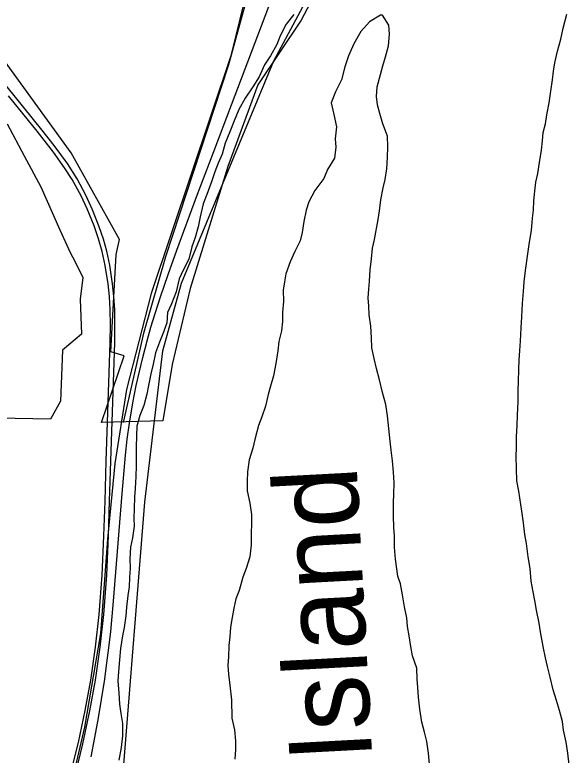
# Model space of a CAD drawing. Extents: x 0 to 34, y 0 to 22.
# Drawn here: x 7.567 to 8.202, y 16.72 to 17.57 of the extents above; entities that cross this region are included whole.
import ezdxf

# ---------------------------------------------------------------- set-up
doc = ezdxf.new("R2010")
doc.units = 0
for name, color, linetype in [('Default', 7, 'Continuous'), ('GM_X_Corporation', 7, 'Continuous'), ('GM_X_County_Road', 7, 'Continuous'), ('GM_X_Major_River', 7, 'Continuous'), ('GM_X_Major_River_Text', 7, 'Continuous'), ('GM_X_Rail_Line', 7, 'Continuous'), ('GM_X_State_Route', 7, 'Continuous'), ('SH_Cut_Line', 7, 'Continuous')]:
    doc.layers.add(name, color=color, linetype=linetype)

msp = doc.modelspace()

# ---------------------------------------------------------------- linework, layer by layer
at = {"layer": 'Default'}
for p, q in [((7.86366, 17.51672), (7.97349, 17.7219)), ((7.7577, 17.26163), (7.86366, 17.51672)), ((7.73627, 17.18403), (7.7577, 17.26163)), ((7.7159, 17.01051), (7.73627, 17.18403)), ((7.68935, 16.68153), (7.7159, 17.01051))]:
    msp.add_line(p, q, dxfattribs=at)
at = {"layer": 'GM_X_Corporation'}
for p, q in [((7.93353, 17.63557), (7.89491, 17.56358)), ((7.89491, 17.56358), (7.84536, 17.48933)), ((7.63141, 17.41126), (7.52859, 17.55268)), ((7.84536, 17.48933), (7.81084, 17.39577)), ((7.55793, 17.44464), (7.57731, 17.40799)), ((7.57731, 17.40799), (7.59665, 17.37247)), ((7.68691, 17.31187), (7.63141, 17.41126)), ((7.81084, 17.39577), (7.76795, 17.25553)), ((7.59665, 17.37247), (7.61832, 17.32296)), ((7.61832, 17.32296), (7.63014, 17.29709)), ((7.68292, 17.29462), (7.68691, 17.31187)), ((7.63014, 17.29709), (7.63539, 17.287)), ((7.67664, 17.18295), (7.68292, 17.29462)), ((7.63539, 17.287), (7.64472, 17.26828)), ((7.64472, 17.26828), (7.64172, 17.24345)), ((7.76795, 17.25553), (7.74724, 17.1685)), ((7.64172, 17.24345), (7.64301, 17.20316)), ((7.64301, 17.20316), (7.62123, 17.18496)), ((7.62123, 17.18496), (7.61894, 17.1263)), ((7.66628, 17.10174), (7.69195, 17.1785)), ((7.69195, 17.1785), (7.67664, 17.18295)), ((7.74724, 17.1685), (7.73642, 17.10386)), ((7.61894, 17.1263), (7.60746, 17.10576)), ((7.60746, 17.10576), (7.42768, 17.10867)), ((7.73642, 17.10386), (7.66628, 17.10174))]:
    msp.add_line(p, q, dxfattribs=at)
at = {"layer": 'GM_X_County_Road'}
for p, q in [((7.8123, 17.51256), (7.83068, 17.5807)), ((7.74001, 17.29247), (7.8123, 17.51256)), ((7.71492, 17.20592), (7.74001, 17.29247)), ((7.6914, 17.10177), (7.71492, 17.20592))]:
    msp.add_line(p, q, dxfattribs=at)
at = {"layer": 'GM_X_Major_River'}
for p, q in [((7.8868, 17.57007), (7.87791, 17.55888)), ((7.98609, 17.56928), (7.97334, 17.56182)), ((7.98836, 17.56933), (7.98609, 17.56928)), ((7.99577, 17.55768), (7.98836, 17.56933)), ((8.19553, 17.55423), (8.19978, 17.57027)), ((7.97334, 17.56182), (7.96332, 17.55061)), ((7.87791, 17.55888), (7.87095, 17.54545)), ((7.99634, 17.54743), (7.99577, 17.55768)), ((8.19273, 17.54164), (8.19553, 17.55423)), ((7.87095, 17.54545), (7.86735, 17.5355)), ((7.96332, 17.55061), (7.95562, 17.5364)), ((7.99507, 17.53411), (7.99634, 17.54743)), ((7.86735, 17.5355), (7.86001, 17.52244)), ((7.95562, 17.5364), (7.94944, 17.52261)), ((8.1892, 17.52789), (8.19273, 17.54164)), ((7.99189, 17.52151), (7.99507, 17.53411)), ((8.18603, 17.51453), (8.1892, 17.52789)), ((7.86001, 17.52244), (7.853, 17.51242)), ((7.94944, 17.52261), (7.94512, 17.50998)), ((7.98867, 17.51118), (7.99189, 17.52151)), ((7.853, 17.51242), (7.84681, 17.49863)), ((7.94512, 17.50998), (7.94123, 17.49509)), ((7.9823, 17.48712), (7.98867, 17.51118)), ((8.18431, 17.50499), (8.18603, 17.51453)), ((8.18336, 17.4951), (8.18431, 17.50499)), ((7.84681, 17.49863), (7.83982, 17.48709)), ((7.94123, 17.49509), (7.93428, 17.48127)), ((8.18133, 17.48214), (8.18336, 17.4951)), ((7.83982, 17.48709), (7.83097, 17.474)), ((7.98137, 17.47608), (7.9823, 17.48712)), ((7.93428, 17.48127), (7.92959, 17.46864)), ((7.98268, 17.46622), (7.98137, 17.47608)), ((8.1793, 17.46879), (8.18133, 17.48214)), ((7.83097, 17.474), (7.82363, 17.46094)), ((7.92959, 17.46864), (7.93249, 17.45539)), ((8.1769, 17.45507), (8.1793, 17.46879)), ((7.82363, 17.46094), (7.81819, 17.44791)), ((7.98514, 17.45639), (7.98268, 17.46622)), ((7.93249, 17.45539), (7.9354, 17.441)), ((7.98876, 17.44467), (7.98514, 17.45639)), ((8.17519, 17.44477), (8.1769, 17.45507)), ((7.81819, 17.44791), (7.81312, 17.43528)), ((7.99395, 17.43033), (7.98876, 17.44467)), ((8.17273, 17.43446), (8.17519, 17.44477)), ((7.81312, 17.43528), (7.80805, 17.42225)), ((7.9354, 17.441), (7.93414, 17.4273)), ((8.17177, 17.42494), (8.17273, 17.43446)), ((7.93414, 17.4273), (7.93469, 17.41781)), ((7.99456, 17.41818), (7.99395, 17.43033)), ((8.17083, 17.41428), (8.17177, 17.42494)), ((7.80805, 17.42225), (7.80449, 17.40964)), ((7.93469, 17.41781), (7.93341, 17.40524)), ((7.99402, 17.406), (7.99456, 17.41818)), ((7.80449, 17.40964), (7.79976, 17.39929)), ((8.16844, 17.40018), (8.17083, 17.41428)), ((7.79976, 17.39929), (7.79615, 17.38934)), ((7.93341, 17.40524), (7.92531, 17.39216)), ((7.99312, 17.39306), (7.99402, 17.406)), ((8.1664, 17.3876), (8.16844, 17.40018)), ((7.92531, 17.39216), (7.92096, 17.38182)), ((7.99145, 17.38087), (7.99312, 17.39306)), ((7.79615, 17.38934), (7.79255, 17.37901)), ((8.1643, 17.37767), (8.1664, 17.3876)), ((7.79255, 17.37901), (7.78678, 17.36332)), ((7.92096, 17.38182), (7.9106, 17.36794)), ((7.98898, 17.37132), (7.99145, 17.38087)), ((8.16298, 17.36739), (8.1643, 17.37767)), ((7.9106, 17.36794), (7.90401, 17.35527)), ((7.98658, 17.35721), (7.98898, 17.37132)), ((8.16205, 17.35635), (8.16298, 17.36739)), ((7.78678, 17.36332), (7.7828, 17.35298)), ((7.98492, 17.34464), (7.98658, 17.35721)), ((7.7828, 17.35298), (7.77929, 17.33771)), ((7.90401, 17.35527), (7.90078, 17.3457)), ((8.16148, 17.34569), (8.16205, 17.35635)), ((7.90078, 17.3457), (7.89799, 17.33235)), ((7.98321, 17.33472), (7.98492, 17.34464)), ((8.16052, 17.33617), (8.16148, 17.34569)), ((7.77929, 17.33771), (7.77685, 17.32625)), ((7.89799, 17.33235), (7.89633, 17.31977)), ((7.97908, 17.31183), (7.98321, 17.33472)), ((8.15926, 17.32208), (8.16052, 17.33617)), ((7.77685, 17.32625), (7.77366, 17.31403)), ((7.89633, 17.31977), (7.89385, 17.31022)), ((8.15686, 17.30873), (8.15926, 17.32208)), ((7.77366, 17.31403), (7.76969, 17.30331)), ((7.89385, 17.31022), (7.88764, 17.29794)), ((7.97699, 17.30191), (7.97908, 17.31183)), ((8.15483, 17.29539), (8.15686, 17.30873)), ((7.76969, 17.30331), (7.76616, 17.28918)), ((7.88764, 17.29794), (7.88255, 17.28606)), ((7.9757, 17.28972), (7.97699, 17.30191)), ((7.76616, 17.28918), (7.75965, 17.27662)), ((7.97404, 17.27715), (7.9757, 17.28972)), ((8.15215, 17.27634), (8.15483, 17.29539)), ((7.88255, 17.28606), (7.87749, 17.27266)), ((7.75965, 17.27662), (7.75526, 17.26661)), ((7.87749, 17.27266), (7.87577, 17.26312)), ((7.97352, 17.26421), (7.97404, 17.27715)), ((8.15087, 17.26339), (8.15215, 17.27634)), ((7.75526, 17.26661), (7.75169, 17.25165)), ((7.97255, 17.25469), (7.97352, 17.26421)), ((8.14994, 17.25235), (8.15087, 17.26339)), ((7.87577, 17.26312), (7.87443, 17.2536)), ((7.75169, 17.25165), (7.74626, 17.23786)), ((7.87443, 17.2536), (7.87467, 17.24067)), ((7.97198, 17.2448), (7.97255, 17.25469)), ((8.14906, 17.23827), (8.14994, 17.25235)), ((7.74626, 17.23786), (7.74189, 17.22828)), ((7.87467, 17.24067), (7.87376, 17.22849)), ((7.97253, 17.23531), (7.97198, 17.2448)), ((8.1482, 17.22305), (8.14906, 17.23827)), ((7.97309, 17.22543), (7.97253, 17.23531)), ((7.74189, 17.22828), (7.74098, 17.2161)), ((7.87376, 17.22849), (7.87357, 17.21785)), ((7.97484, 17.21254), (7.97309, 17.22543)), ((8.1473, 17.21048), (8.1482, 17.22305)), ((7.74098, 17.2161), (7.73738, 17.20538)), ((7.87357, 17.21785), (7.87263, 17.20718)), ((7.97585, 17.19888), (7.97484, 17.21254)), ((7.73738, 17.20538), (7.73267, 17.19389)), ((7.87263, 17.20718), (7.86944, 17.19496)), ((8.14644, 17.19526), (8.1473, 17.21048)), ((7.97606, 17.18747), (7.97585, 17.19888)), ((7.73267, 17.19389), (7.72797, 17.18164)), ((7.86944, 17.19496), (7.8685, 17.1843)), ((7.97894, 17.17537), (7.97606, 17.18747)), ((8.14588, 17.18461), (8.14644, 17.19526)), ((7.72797, 17.18164), (7.72518, 17.16866)), ((7.8685, 17.1843), (7.86612, 17.16943)), ((8.14494, 17.17357), (8.14588, 17.18461)), ((7.98142, 17.16401), (7.97894, 17.17537)), ((8.14476, 17.16292), (8.14494, 17.17357)), ((7.72518, 17.16866), (7.72273, 17.15759)), ((7.86612, 17.16943), (7.86335, 17.15531)), ((7.98508, 17.15077), (7.98142, 17.16401)), ((8.14427, 17.14847), (8.14476, 17.16292)), ((7.72273, 17.15759), (7.71994, 17.14423)), ((7.86335, 17.15531), (7.85978, 17.14346)), ((7.98837, 17.13639), (7.98508, 17.15077)), ((8.14407, 17.13896), (8.14427, 17.14847)), ((7.71994, 17.14423), (7.71823, 17.13431)), ((7.85978, 17.14346), (7.8573, 17.13391)), ((7.99204, 17.1224), (7.98837, 17.13639)), ((8.14393, 17.12603), (8.14407, 17.13896)), ((7.71823, 17.13431), (7.71468, 17.12132)), ((7.8573, 17.13391), (7.85414, 17.12054)), ((7.71468, 17.12132), (7.70996, 17.10983)), ((7.85414, 17.12054), (7.84982, 17.1083)), ((7.99417, 17.10951), (7.99204, 17.1224)), ((8.14308, 17.11044), (8.14393, 17.12603)), ((8.14292, 17.09827), (8.14308, 17.11044)), ((7.70996, 17.10983), (7.70678, 17.0976)), ((7.84982, 17.1083), (7.84621, 17.09835)), ((7.99557, 17.0951), (7.99417, 17.10951)), ((7.70678, 17.0976), (7.70622, 17.08657)), ((7.84621, 17.09835), (7.84196, 17.0823)), ((7.99698, 17.0803), (7.99557, 17.0951)), ((8.14202, 17.08533), (8.14292, 17.09827)), ((7.70622, 17.08657), (7.7057, 17.07363)), ((8.14187, 17.07278), (8.14202, 17.08533)), ((7.84196, 17.0823), (7.83949, 17.07237)), ((7.99831, 17.07006), (7.99698, 17.0803)), ((7.7057, 17.07363), (7.7059, 17.06261)), ((7.83949, 17.07237), (7.83557, 17.05899)), ((7.99967, 17.05792), (7.99831, 17.07006)), ((8.14167, 17.06328), (8.14187, 17.07278)), ((7.7059, 17.06261), (7.70572, 17.05197)), ((8.14194, 17.04884), (8.14167, 17.06328)), ((7.70572, 17.05197), (7.70556, 17.0398)), ((7.83557, 17.05899), (7.83355, 17.04527)), ((8.00104, 17.04502), (7.99967, 17.05792)), ((7.83355, 17.04527), (7.83298, 17.03461)), ((8.00165, 17.03249), (8.00104, 17.04502)), ((8.14257, 17.03479), (8.14194, 17.04884)), ((7.70556, 17.0398), (7.70468, 17.0261)), ((7.83298, 17.03461), (7.83319, 17.02359)), ((8.14469, 17.02304), (8.14257, 17.03479)), ((7.70468, 17.0261), (7.7041, 17.01658)), ((8.00151, 17.01957), (8.00165, 17.03249)), ((7.83319, 17.02359), (7.8361, 17.00921)), ((8.00093, 17.01005), (8.00151, 17.01957)), ((8.14814, 17.00031), (8.14469, 17.02304)), ((7.7041, 17.01658), (7.70359, 17.00289)), ((7.8361, 17.00921), (7.83824, 16.99632)), ((8.00083, 16.99485), (8.00093, 17.01005)), ((7.70359, 17.00289), (7.70303, 16.99224)), ((8.1499, 16.98666), (8.14814, 17.00031)), ((7.70303, 16.99224), (7.70358, 16.98275)), ((7.83824, 16.99632), (7.83803, 16.98682)), ((8.00145, 16.98156), (8.00083, 16.99485)), ((7.83803, 16.98682), (7.83789, 16.97389)), ((8.15167, 16.97339), (8.1499, 16.98666)), ((7.70358, 16.98275), (7.70155, 16.9694)), ((8.00201, 16.97168), (8.00145, 16.98156)), ((7.70155, 16.9694), (7.69948, 16.95872)), ((7.83789, 16.97389), (7.83774, 16.96134)), ((8.00225, 16.95877), (8.00201, 16.97168)), ((8.15337, 16.96316), (8.15167, 16.97339)), ((7.69948, 16.95872), (7.69859, 16.9454)), ((7.83774, 16.96134), (7.8361, 16.94763)), ((8.00326, 16.9451), (8.00225, 16.95877)), ((8.15555, 16.94762), (8.15337, 16.96316)), ((7.69859, 16.9454), (7.69916, 16.93477)), ((7.8361, 16.94763), (7.83218, 16.93425)), ((8.0059, 16.92539), (8.00326, 16.9451)), ((8.15769, 16.93436), (8.15555, 16.94762)), ((7.69916, 16.93477), (7.69822, 16.92411)), ((7.83218, 16.93425), (7.82819, 16.92429)), ((8.15872, 16.91993), (8.15769, 16.93436)), ((7.69822, 16.92411), (7.69766, 16.91346)), ((7.82819, 16.92429), (7.82393, 16.90901)), ((8.00909, 16.91671), (8.0059, 16.92539)), ((8.01122, 16.90421), (8.00909, 16.91671)), ((8.16122, 16.90744), (8.15872, 16.91993)), ((7.69766, 16.91346), (7.69633, 16.90355)), ((7.82393, 16.90901), (7.82032, 16.89944)), ((8.16292, 16.89759), (8.16122, 16.90744)), ((7.69633, 16.90355), (7.69469, 16.88983)), ((7.82032, 16.89944), (7.81786, 16.88875)), ((8.01375, 16.89019), (8.01122, 16.90421)), ((7.69469, 16.88983), (7.69411, 16.87994)), ((8.01626, 16.8777), (8.01375, 16.89019)), ((8.16501, 16.88661), (8.16292, 16.89759)), ((7.81786, 16.88875), (7.81579, 16.87807)), ((8.16795, 16.87146), (8.16501, 16.88661)), ((7.69411, 16.87994), (7.69208, 16.8666)), ((7.81579, 16.87807), (7.8141, 16.86702)), ((8.01719, 16.86784), (8.01626, 16.8777)), ((7.69208, 16.8666), (7.69037, 16.85707)), ((7.8141, 16.86702), (7.81316, 16.85598)), ((8.01891, 16.85723), (8.01719, 16.86784)), ((8.16965, 16.86162), (8.16795, 16.87146)), ((7.69037, 16.85707), (7.68798, 16.84258)), ((7.81316, 16.85598), (7.81221, 16.84608)), ((8.02065, 16.84472), (8.01891, 16.85723)), ((8.17261, 16.84495), (8.16965, 16.86162)), ((7.68798, 16.84258), (7.68671, 16.82963)), ((7.81221, 16.84608), (7.81169, 16.83315)), ((8.02275, 16.83412), (8.02065, 16.84472)), ((8.17513, 16.8317), (8.17261, 16.84495)), ((7.81169, 16.83315), (7.81112, 16.82288)), ((8.02755, 16.82015), (8.02275, 16.83412)), ((8.17758, 16.82186), (8.17513, 16.8317)), ((7.68671, 16.82963), (7.68544, 16.81631)), ((7.81112, 16.82288), (7.81169, 16.81301)), ((8.18046, 16.80976), (8.17758, 16.82186)), ((7.68544, 16.81631), (7.68489, 16.8049)), ((8.02817, 16.80724), (8.02755, 16.82015)), ((7.68489, 16.8049), (7.68589, 16.79162)), ((7.81169, 16.81301), (7.81343, 16.8005)), ((8.02872, 16.79775), (8.02817, 16.80724)), ((8.18414, 16.79501), (8.18046, 16.80976)), ((7.81343, 16.8005), (7.81526, 16.78382)), ((8.02969, 16.78675), (8.02872, 16.79775)), ((7.68589, 16.79162), (7.68689, 16.77871)), ((8.18778, 16.78292), (8.18414, 16.79501)), ((7.81526, 16.78382), (7.81565, 16.76254)), ((8.03108, 16.7731), (8.02969, 16.78675)), ((8.1914, 16.77159), (8.18778, 16.78292)), ((7.68689, 16.77871), (7.68822, 16.7681)), ((8.03363, 16.75795), (8.03108, 16.7731)), ((8.19467, 16.75873), (8.1914, 16.77159)), ((7.68822, 16.7681), (7.69034, 16.75636)), ((7.81565, 16.76254), (7.81855, 16.7493)), ((7.69034, 16.75636), (7.69022, 16.7423)), ((8.0365, 16.7466), (8.03363, 16.75795)), ((8.19599, 16.74888), (8.19467, 16.75873)), ((7.81855, 16.7493), (7.81993, 16.7364)), ((8.03934, 16.73602), (8.0365, 16.7466)), ((8.1989, 16.73488), (8.19599, 16.74888)), ((7.69022, 16.7423), (7.68857, 16.72897)), ((7.68857, 16.72897), (7.68581, 16.71448)), ((7.81993, 16.7364), (7.81973, 16.72652)), ((8.04111, 16.72237), (8.03934, 16.73602)), ((8.20103, 16.72238), (8.1989, 16.73488)), ((7.81973, 16.72652), (7.81918, 16.71549)), ((8.0421, 16.70985), (8.04111, 16.72237)), ((8.20241, 16.70911), (8.20103, 16.72238))]:
    msp.add_line(p, q, dxfattribs=at)
at = {"layer": 'GM_X_Rail_Line'}
for p, q in [((7.83026, 17.58703), (7.81446, 17.52263)), ((7.83822, 17.52667), (7.85811, 17.57941)), ((7.81446, 17.52263), (7.72325, 17.24992)), ((7.81527, 17.46622), (7.83822, 17.52667)), ((7.79508, 17.41299), (7.81527, 17.46622)), ((7.77519, 17.36074), (7.79508, 17.41299)), ((7.75254, 17.29979), (7.77519, 17.36074)), ((7.74244, 17.27189), (7.75254, 17.29979)), ((7.73364, 17.24617), (7.74244, 17.27189)), ((7.72325, 17.24992), (7.69464, 17.13967)), ((7.7276, 17.22697), (7.73364, 17.24617)), ((7.72275, 17.21124), (7.7276, 17.22697)), ((7.7184, 17.19551), (7.72275, 17.21124)), ((7.71355, 17.17661), (7.7184, 17.19551)), ((7.70593, 17.14416), (7.71355, 17.17661)), ((7.69464, 17.13967), (7.68152, 17.0547)), ((7.70217, 17.12447), (7.70593, 17.14416)), ((7.69822, 17.10121), (7.70217, 17.12447)), ((7.69564, 17.08261), (7.69822, 17.10121)), ((7.6937, 17.06447), (7.69564, 17.08261)), ((7.68985, 17.02037), (7.6937, 17.06447)), ((7.68152, 17.0547), (7.67301, 16.9679)), ((7.68638, 16.97751), (7.68985, 17.02037)), ((7.67952, 16.89214), (7.68638, 16.97751)), ((7.67301, 16.9679), (7.66489, 16.8598)), ((7.67665, 16.86207), (7.67952, 16.89214)), ((7.66489, 16.8598), (7.64651, 16.75227)), ((7.67446, 16.84318), (7.67665, 16.86207)), ((7.67229, 16.82615), (7.67446, 16.84318)), ((7.66982, 16.80725), (7.67229, 16.82615)), ((7.66626, 16.7839), (7.66982, 16.80725)), ((7.6625, 16.76312), (7.66626, 16.7839)), ((7.65844, 16.74026), (7.6625, 16.76312)), ((7.64651, 16.75227), (7.62454, 16.6562)), ((7.65428, 16.7183), (7.65844, 16.74026))]:
    msp.add_line(p, q, dxfattribs=at)
at = {"layer": 'GM_X_State_Route'}
for p, q in [((7.59764, 17.43788), (7.54044, 17.50829)), ((7.59223, 17.43623), (7.55934, 17.47669)), ((7.61102, 17.41216), (7.59223, 17.43623)), ((7.61196, 17.41974), (7.59764, 17.43788)), ((7.62716, 17.39897), (7.61196, 17.41974)), ((7.62381, 17.3942), (7.61102, 17.41216)), ((7.63248, 17.38058), (7.62381, 17.3942)), ((7.63813, 17.38143), (7.62716, 17.39897)), ((7.64282, 17.36189), (7.63248, 17.38058)), ((7.64831, 17.36261), (7.63813, 17.38143)), ((7.64976, 17.34717), (7.64282, 17.36189)), ((7.65589, 17.34607), (7.64831, 17.36261)), ((7.65764, 17.32744), (7.64976, 17.34717)), ((7.66357, 17.32659), (7.65589, 17.34607)), ((7.6626, 17.31251), (7.65764, 17.32744)), ((7.66826, 17.31215), (7.66357, 17.32659)), ((7.66682, 17.29819), (7.6626, 17.31251)), ((7.67208, 17.29832), (7.66826, 17.31215)), ((7.67038, 17.28216), (7.66682, 17.29819)), ((7.67564, 17.28229), (7.67208, 17.29832)), ((7.67364, 17.261), (7.67038, 17.28216)), ((7.67889, 17.26114), (7.67564, 17.28229)), ((7.67517, 17.24634), (7.67364, 17.261)), ((7.68042, 17.24647), (7.67889, 17.26114)), ((7.68126, 17.23118), (7.68042, 17.24647)), ((7.676, 17.23105), (7.67517, 17.24634)), ((7.67628, 17.21423), (7.676, 17.23105)), ((7.68153, 17.21436), (7.68126, 17.23118)), ((7.67607, 17.19338), (7.67628, 17.21423)), ((7.68133, 17.19351), (7.68153, 17.21436)), ((7.67461, 17.14792), (7.67607, 17.19338)), ((7.67987, 17.14806), (7.68133, 17.19351)), ((7.67301, 17.1024), (7.67461, 17.14792)), ((7.67827, 17.10253), (7.67987, 17.14806)), ((7.67155, 17.05764), (7.67301, 17.1024)), ((7.67681, 17.05777), (7.67827, 17.10253)), ((7.67016, 17.01177), (7.67155, 17.05764)), ((7.67575, 17.02287), (7.67681, 17.05777)), ((7.67542, 17.0119), (7.67575, 17.02287)), ((7.66877, 16.97187), (7.67016, 17.01177)), ((7.67403, 16.97201), (7.67542, 17.0119)), ((7.66689, 16.92669), (7.66877, 16.97187)), ((7.67215, 16.92683), (7.67403, 16.97201)), ((7.66349, 16.88159), (7.66689, 16.92669)), ((7.66875, 16.88172), (7.67215, 16.92683)), ((7.65925, 16.84392), (7.66349, 16.88159)), ((7.66451, 16.84405), (7.66875, 16.88172)), ((7.65383, 16.80625), (7.65925, 16.84392)), ((7.65908, 16.80638), (7.66451, 16.84405)), ((7.64746, 16.77156), (7.65383, 16.80625)), ((7.65276, 16.77086), (7.65908, 16.80638)), ((7.63963, 16.73471), (7.64746, 16.77156)), ((7.6447, 16.73319), (7.65276, 16.77086)), ((7.63065, 16.69832), (7.63963, 16.73471)), ((7.63559, 16.69608), (7.6447, 16.73319))]:
    msp.add_line(p, q, dxfattribs=at)
at = {"layer": 'SH_Cut_Line'}
for p, q in [((7.86366, 17.51672), (7.97349, 17.7219)), ((7.7577, 17.26163), (7.86366, 17.51672)), ((7.73627, 17.18403), (7.7577, 17.26163)), ((7.7159, 17.01051), (7.73627, 17.18403)), ((7.68935, 16.68153), (7.7159, 17.01051))]:
    msp.add_line(p, q, dxfattribs=at)

# ---------------------------------------------------------------- texts
at = {"layer": 'GM_X_Major_River_Text'}
msp.add_text('Island', height=0.09484, rotation=93.06639, dxfattribs=at).set_placement((7.97676, 16.71533))

doc.saveas('drawing.dxf')
